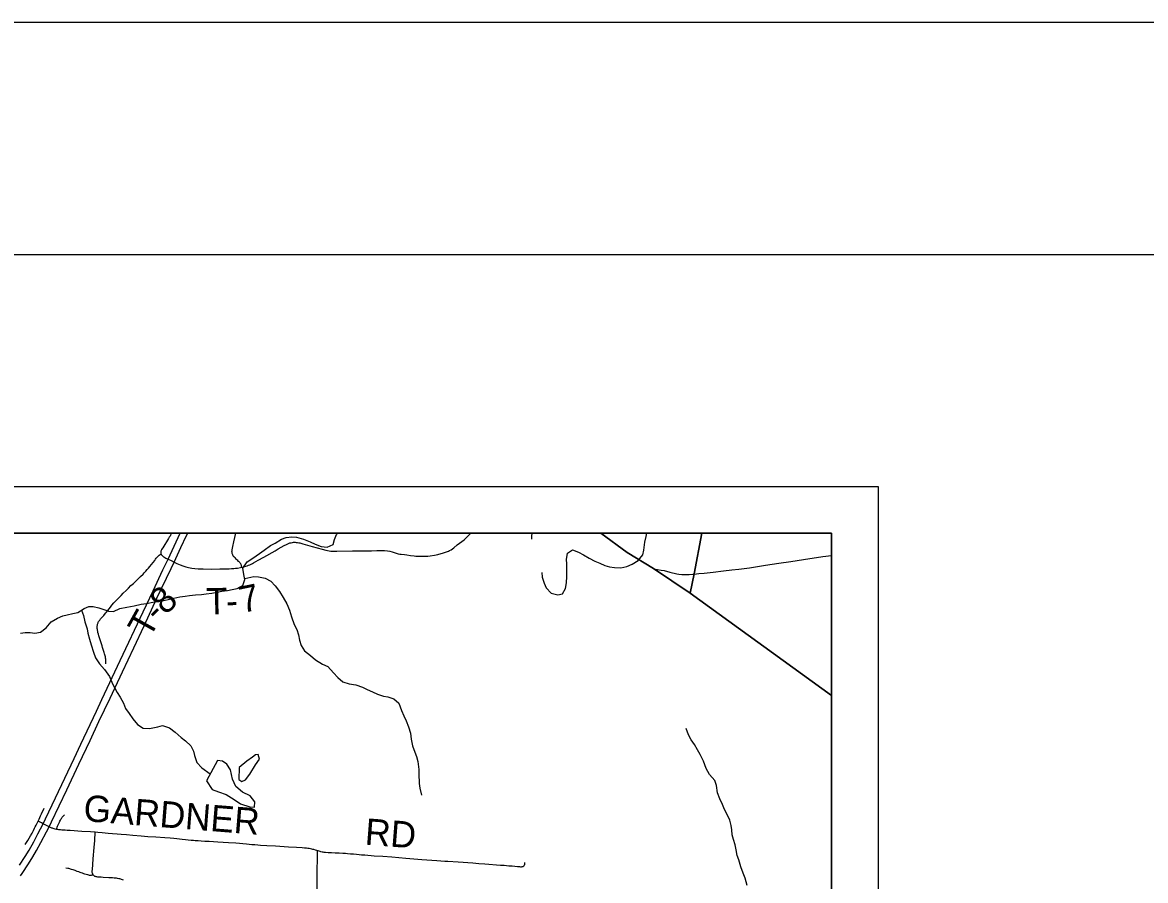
# Model space of a CAD drawing. Extents: x 0 to 34, y 0 to 22.
# Drawn here: x 7.37 to 9.791, y 20.151 to 22 of the extents above; entities that cross this region are included whole.
import ezdxf

# ---------------------------------------------------------------- set-up
doc = ezdxf.new("R2010")
doc.units = 0
for name, color, linetype in [('Default', 7, 'Continuous'), ('GM_X_Minor_Lake', 7, 'Continuous'), ('GM_X_Minor_River', 7, 'Continuous'), ('GM_X_Township_Road', 7, 'Continuous'), ('GM_X_Township_Road_Text', 7, 'Continuous'), ('GM_X_US_Route', 7, 'Continuous'), ('SH_Border', 7, 'Continuous'), ('SH_Cut_Line', 7, 'Continuous'), ('SH_Data', 7, 'Continuous')]:
    doc.layers.add(name, color=color, linetype=linetype)

msp = doc.modelspace()

# ---------------------------------------------------------------- linework, layer by layer
at = {"layer": 'Default'}
msp.add_lwpolyline([(9.1142, 17.7402), (9.1142, 20.5497), (8.8095, 20.7701), (8.7304, 20.823), (8.6734, 20.858), (8.6167, 20.8996), (2.3571, 20.8996)], dxfattribs=at)
for points in [[(8.8345, 20.8996), (8.6167, 20.8996), (8.6734, 20.858), (8.7304, 20.823), (8.8095, 20.7701), (8.8178, 20.8117)], [(9.1142, 20.5497), (9.1142, 20.8996), (8.8345, 20.8996), (8.8178, 20.8117), (8.8095, 20.7701)]]:
    msp.add_lwpolyline(points, close=True, dxfattribs=at)
at = {"layer": 'GM_X_Minor_Lake'}
for points in [[(7.7666, 20.3654), (7.7788, 20.3471), (7.7928, 20.342), (7.8094, 20.3364), (7.8263, 20.3256), (7.8399, 20.3159), (7.8602, 20.3092), (7.8705, 20.3087), (7.8706, 20.3201), (7.8605, 20.3335), (7.8443, 20.3413), (7.8301, 20.3532), (7.8227, 20.3689), (7.8184, 20.389), (7.8106, 20.4016), (7.8012, 20.4078), (7.7906, 20.4095)], [(7.7906, 20.4095), (7.7666, 20.3654)], [(7.8367, 20.3683), (7.8431, 20.3644), (7.8511, 20.3677), (7.8604, 20.3797), (7.872, 20.3997), (7.8809, 20.4121), (7.8784, 20.4223), (7.8727, 20.4217), (7.8661, 20.4164), (7.8535, 20.4079), (7.8371, 20.3945)], [(7.8371, 20.3945), (7.8367, 20.3683)]]:
    msp.add_lwpolyline(points, dxfattribs=at)
at = {"layer": 'GM_X_Minor_River'}
for points in [[(7.3968, 20.684), (7.4093, 20.6861), (7.4212, 20.6954), (7.4316, 20.7085), (7.4453, 20.7163), (7.4572, 20.7211), (7.4667, 20.7236), (7.4788, 20.7265), (7.4891, 20.7282), (7.5029, 20.7372), (7.5128, 20.7412), (7.5226, 20.7414), (7.5347, 20.7386), (7.5453, 20.7351), (7.5555, 20.7311), (7.5665, 20.7306), (7.5798, 20.7369), (7.595, 20.7401), (7.611, 20.7429), (7.6258, 20.7461), (7.6372, 20.7475), (7.6509, 20.7503), (7.6608, 20.7517), (7.671, 20.7535), (7.6843, 20.7567), (7.6961, 20.7592), (7.7094, 20.7621), (7.7204, 20.7634), (7.7303, 20.7648), (7.7428, 20.7662), (7.7561, 20.7675), (7.766, 20.7689), (7.7781, 20.7703), (7.7895, 20.772), (7.7998, 20.7741), (7.8119, 20.7759), (7.8218, 20.7776), (7.8329, 20.7801), (7.8454, 20.7864), (7.8494, 20.7996), (7.8473, 20.8103), (7.8452, 20.8236), (7.8541, 20.8375), (7.8667, 20.8457), (7.8812, 20.8553), (7.8908, 20.8624), (7.9049, 20.8725), (7.9145, 20.878), (7.9282, 20.8862), (7.9385, 20.8902), (7.9507, 20.8912), (7.9605, 20.8907), (7.9756, 20.8863), (7.9899, 20.8804), (8.0009, 20.8754), (8.0137, 20.8706), (8.0266, 20.8689), (8.0395, 20.8748), (8.0423, 20.8858), (8.0466, 20.8967), (8.0496, 20.8996)], [(8.4683, 20.8861), (8.4682, 20.893), (8.4687, 20.8996)], [(8.4895, 20.8146), (8.4902, 20.8048), (8.4942, 20.7915), (8.4986, 20.7815), (8.5098, 20.77), (8.5238, 20.7664), (8.5337, 20.7689), (8.5403, 20.7799), (8.5427, 20.792), (8.5436, 20.8056), (8.5434, 20.82), (8.5436, 20.8329), (8.543, 20.8428), (8.5447, 20.856), (8.5558, 20.8634), (8.5682, 20.8583), (8.5791, 20.8525), (8.5912, 20.8452), (8.6036, 20.8393), (8.6145, 20.8346), (8.6251, 20.8299), (8.6353, 20.8271), (8.6463, 20.8255), (8.6599, 20.8249), (8.6724, 20.8274), (8.6843, 20.8322), (8.6969, 20.8407), (8.7069, 20.8527), (8.7093, 20.8629), (8.7118, 20.8796), (8.7142, 20.8921), (8.7161, 20.8996)], [(7.849, 20.8018), (7.8684, 20.8058), (7.8787, 20.8049), (7.8934, 20.8021), (7.9055, 20.7959), (7.9144, 20.7859), (7.9241, 20.7736), (7.9319, 20.7606), (7.9401, 20.7469), (7.9456, 20.7331), (7.9496, 20.7191), (7.9555, 20.7023), (7.9614, 20.6916), (7.965, 20.6802), (7.9675, 20.6688), (7.9708, 20.6574), (7.9779, 20.6459), (7.9906, 20.6355), (8.0019, 20.6266), (8.0169, 20.6173), (8.0282, 20.6118), (8.0406, 20.5984), (8.0499, 20.5884), (8.0608, 20.5788), (8.0744, 20.5748), (8.0884, 20.5724), (8.1031, 20.5676), (8.1133, 20.5622), (8.1246, 20.5575), (8.1351, 20.5524), (8.148, 20.5481), (8.1578, 20.5464), (8.1703, 20.5421), (8.1815, 20.5328), (8.187, 20.5172), (8.1918, 20.5054), (8.197, 20.4947), (8.2021, 20.4817), (8.2065, 20.468), (8.2078, 20.4551), (8.2111, 20.4407), (8.2158, 20.4273), (8.2195, 20.4178), (8.222, 20.4072), (8.2241, 20.3901), (8.2247, 20.3806), (8.2252, 20.3601), (8.2262, 20.3498), (8.2302, 20.335)], [(7.4971, 20.7334), (7.5015, 20.7216), (7.5048, 20.7083), (7.5095, 20.6935), (7.5113, 20.6836), (7.5149, 20.6706), (7.5182, 20.6585), (7.5233, 20.6429), (7.5277, 20.6303), (7.5358, 20.618), (7.5467, 20.6058), (7.5575, 20.5904), (7.5641, 20.5748), (7.5741, 20.5557), (7.5808, 20.5458), (7.5875, 20.5332), (7.5922, 20.5217), (7.5997, 20.511), (7.6079, 20.4991), (7.618, 20.4869), (7.63, 20.4791), (7.6436, 20.4782), (7.6615, 20.4817), (7.6722, 20.485), (7.6869, 20.4799), (7.6989, 20.4706), (7.712, 20.4591), (7.7218, 20.4521), (7.733, 20.441), (7.7386, 20.4295), (7.7411, 20.42), (7.7462, 20.4051), (7.7567, 20.3933), (7.7748, 20.3806)], [(7.3661, 20.684), (7.3759, 20.685), (7.3866, 20.6849), (7.3968, 20.684)], [(8.9318, 20.1403), (8.9278, 20.1559), (8.9234, 20.1665), (8.9182, 20.1799), (8.9139, 20.1951), (8.9106, 20.2046), (8.9081, 20.2172), (8.9063, 20.2274), (8.9027, 20.2392), (8.8998, 20.2495), (8.8988, 20.2598), (8.8974, 20.2693), (8.8945, 20.2807), (8.8897, 20.2917), (8.883, 20.304), (8.8786, 20.3143), (8.8735, 20.3268), (8.8683, 20.3398), (8.8663, 20.3554), (8.8626, 20.3664), (8.851, 20.3791), (8.844, 20.3921), (8.8381, 20.4077), (8.8307, 20.4226), (8.8248, 20.4325), (8.8188, 20.4436), (8.8114, 20.4539), (8.8055, 20.4646), (8.8007, 20.478)]]:
    msp.add_lwpolyline(points, dxfattribs=at)
at = {"layer": 'GM_X_Township_Road'}
for points in [[(7.6911, 20.8996), (7.691, 20.8993), (7.6905, 20.8979), (7.6899, 20.8965), (7.689, 20.8948), (7.6881, 20.8932), (7.6866, 20.8906), (7.6851, 20.8881), (7.6724, 20.868), (7.67, 20.8643), (7.6694, 20.8632), (7.6689, 20.862), (7.6685, 20.8608), (7.6682, 20.8597), (7.6682, 20.8588), (7.6682, 20.8577), (7.6682, 20.8565), (7.6685, 20.8555), (7.6688, 20.8544)], [(7.8426, 20.826), (7.8424, 20.8272), (7.8421, 20.8293), (7.8418, 20.8308), (7.8413, 20.8321), (7.8407, 20.8332), (7.84, 20.8341), (7.8393, 20.835), (7.8385, 20.8359), (7.8371, 20.8373), (7.8358, 20.8385), (7.8343, 20.8401), (7.8323, 20.8419), (7.8305, 20.8436), (7.8289, 20.8451), (7.8273, 20.8467), (7.8262, 20.848), (7.8252, 20.8494), (7.8243, 20.8508), (7.8234, 20.8526), (7.8226, 20.8541), (7.8221, 20.8558), (7.8218, 20.8575), (7.8216, 20.8596), (7.8218, 20.8614), (7.822, 20.8633), (7.8235, 20.8706), (7.8254, 20.8803), (7.8276, 20.89), (7.8302, 20.8996)], [(7.8426, 20.826), (7.8467, 20.827), (7.8545, 20.8292), (7.8575, 20.8302), (7.8603, 20.8313), (7.8632, 20.8325), (7.8657, 20.8337), (7.8681, 20.8351), (7.8778, 20.8408), (7.8902, 20.8478), (7.9145, 20.8616), (7.9215, 20.8657), (7.9339, 20.8727), (7.9389, 20.8752), (7.942, 20.8766), (7.9447, 20.8776), (7.9467, 20.8782), (7.9489, 20.8788), (7.9519, 20.8794), (7.9544, 20.8796), (7.9575, 20.8797), (7.9601, 20.8795), (7.963, 20.8792), (7.9655, 20.8787), (7.9679, 20.8782), (7.9745, 20.8766), (7.9948, 20.8707), (8.0157, 20.8647), (8.0241, 20.8625), (8.0309, 20.8612), (8.0347, 20.8608), (8.0383, 20.8604), (8.0428, 20.8603), (8.0476, 20.8602), (8.0811, 20.8609), (8.1227, 20.8615), (8.1339, 20.8619), (8.1438, 20.8621), (8.1507, 20.8618), (8.1568, 20.8611), (8.1617, 20.8602), (8.1671, 20.8588), (8.1802, 20.8549), (8.1832, 20.8542), (8.1863, 20.8538), (8.1937, 20.8531), (8.1986, 20.8524), (8.2066, 20.8513), (8.214, 20.8503), (8.2179, 20.85), (8.2218, 20.8498), (8.2266, 20.8496), (8.2322, 20.8495), (8.2386, 20.8497), (8.2435, 20.85), (8.2485, 20.8505), (8.2583, 20.8519), (8.2618, 20.8526), (8.2656, 20.8534), (8.2775, 20.8568), (8.284, 20.8589), (8.2886, 20.8607), (8.2908, 20.8618), (8.294, 20.8636), (8.2972, 20.8658), (8.3001, 20.868), (8.3073, 20.8739), (8.3171, 20.8815), (8.3219, 20.8853), (8.3271, 20.8899), (8.3361, 20.8983), (8.3374, 20.8996)], [(7.55, 20.6175), (7.55, 20.6194), (7.55, 20.6215), (7.5499, 20.6238), (7.5497, 20.6259), (7.5495, 20.628), (7.5492, 20.6302), (7.5488, 20.6326), (7.5483, 20.6351), (7.5478, 20.6371), (7.5472, 20.6392), (7.5464, 20.6418), (7.5456, 20.6444), (7.5441, 20.6488), (7.5428, 20.6529), (7.5416, 20.6567), (7.5403, 20.661), (7.5392, 20.6649), (7.5379, 20.6691), (7.5363, 20.6738), (7.535, 20.6778), (7.5338, 20.6815), (7.5327, 20.6856), (7.5322, 20.6881), (7.5319, 20.6899), (7.5316, 20.6917), (7.5314, 20.694), (7.5313, 20.6959), (7.5312, 20.698), (7.5313, 20.6994), (7.5315, 20.7011), (7.5319, 20.7031), (7.5324, 20.7045), (7.5329, 20.706), (7.5334, 20.7074), (7.5342, 20.7088), (7.5351, 20.7102), (7.5365, 20.712), (7.5385, 20.7146), (7.5417, 20.7184), (7.5451, 20.7221), (7.5492, 20.7267), (7.5508, 20.7287), (7.5539, 20.7325), (7.5568, 20.7364), (7.5596, 20.7401), (7.5629, 20.7441), (7.5673, 20.7491), (7.5729, 20.7552), (7.5826, 20.7652), (7.5874, 20.7699), (7.5934, 20.7758), (7.5987, 20.7811), (7.604, 20.7862), (7.6093, 20.791), (7.6205, 20.8016), (7.6246, 20.8056), (7.6299, 20.8109), (7.6326, 20.8139), (7.6358, 20.8174), (7.6391, 20.821), (7.6415, 20.8238), (7.6447, 20.8275), (7.6482, 20.8317), (7.6516, 20.8358), (7.6552, 20.8406), (7.6568, 20.8431), (7.6585, 20.8452), (7.6599, 20.8471), (7.6611, 20.8485), (7.6622, 20.8495), (7.6632, 20.8505), (7.6649, 20.8518), (7.6668, 20.8531), (7.6688, 20.8544)], [(7.6688, 20.8544), (7.6692, 20.8535), (7.67, 20.8524), (7.671, 20.8513), (7.6719, 20.8504), (7.6732, 20.8494), (7.6745, 20.8485), (7.6791, 20.8458), (7.6838, 20.8434)], [(7.6838, 20.8434), (7.6904, 20.8401), (7.6968, 20.8368)], [(8.818, 20.8112), (8.8277, 20.8121), (8.8395, 20.8134), (8.8586, 20.8155), (8.8814, 20.8182), (8.8993, 20.8204), (8.9141, 20.822), (8.9369, 20.8249), (8.9584, 20.8281), (8.9718, 20.8302), (9.0001, 20.8345), (9.0265, 20.8385), (9.0535, 20.8427), (9.0953, 20.8489), (9.1142, 20.8515)], [(7.6968, 20.8368), (7.7031, 20.8338), (7.7097, 20.8308), (7.7158, 20.8286), (7.7219, 20.8269), (7.7281, 20.8254), (7.7315, 20.8246), (7.7348, 20.824), (7.7418, 20.8231), (7.749, 20.8226), (7.7595, 20.8222), (7.7769, 20.822), (7.7955, 20.8222), (7.8154, 20.8227), (7.8204, 20.823), (7.8253, 20.8233), (7.8293, 20.8237), (7.8333, 20.8242), (7.8401, 20.8254), (7.8426, 20.826)], [(8.7307, 20.8225), (8.7469, 20.8197), (8.753, 20.8186), (8.7657, 20.8156), (8.7808, 20.8119), (8.7851, 20.8111), (8.7912, 20.8102), (8.7948, 20.8099), (8.7986, 20.8099), (8.8073, 20.8102), (8.8148, 20.8109), (8.818, 20.8112)], [(7.4041, 20.2788), (7.406, 20.2829), (7.4076, 20.2867), (7.409, 20.2902), (7.4109, 20.2944), (7.4169, 20.3065)], [(7.4437, 20.261), (7.4443, 20.2629), (7.445, 20.2654), (7.4458, 20.2676), (7.4463, 20.269), (7.4471, 20.2707), (7.4485, 20.2738), (7.4498, 20.2766), (7.4509, 20.2788), (7.4518, 20.2806), (7.4531, 20.2828), (7.4542, 20.2847), (7.4559, 20.2872), (7.4573, 20.2889), (7.4583, 20.2901), (7.4592, 20.2911), (7.4606, 20.2923)], [(7.3762, 20.2284), (7.3815, 20.2369), (7.3846, 20.2422), (7.3874, 20.2471), (7.3907, 20.2531), (7.3935, 20.2587), (7.3958, 20.2633), (7.3976, 20.2667), (7.3995, 20.2702), (7.4041, 20.2788)], [(7.4144, 20.2732), (7.4111, 20.2749), (7.4079, 20.2766), (7.4041, 20.2788)], [(7.4277, 20.2665), (7.4217, 20.2696), (7.4144, 20.2732)], [(8.4524, 20.1899), (8.4523, 20.1879), (8.4522, 20.1865), (8.4521, 20.1855), (8.4518, 20.1845), (8.4515, 20.1835), (8.451, 20.1827), (8.4504, 20.1819), (8.4497, 20.1813), (8.4492, 20.1809), (8.4484, 20.1804), (8.4473, 20.1801), (8.4464, 20.1799), (8.4451, 20.1798), (8.4439, 20.1798), (8.4418, 20.1799), (8.4368, 20.1803), (8.4253, 20.1813), (8.4187, 20.182), (8.4082, 20.1829), (8.4006, 20.1834), (8.3665, 20.186), (8.3535, 20.187), (8.3411, 20.1879), (8.3089, 20.1902), (8.2872, 20.1916), (8.2802, 20.192), (8.2719, 20.1926), (8.2631, 20.1932), (8.2526, 20.1939), (8.2308, 20.1956), (8.1967, 20.1982), (8.1664, 20.2007), (8.1466, 20.2022), (8.128, 20.2035), (8.1213, 20.204), (8.1144, 20.2045), (8.1078, 20.205), (8.1011, 20.2055), (8.0958, 20.206), (8.0902, 20.2065), (8.0834, 20.2072), (8.077, 20.2078), (8.0709, 20.2083), (8.0663, 20.2087), (8.0609, 20.209), (8.0525, 20.2094), (8.0444, 20.2097), (8.0362, 20.2101), (8.0289, 20.2106), (8.0232, 20.211), (8.0207, 20.2113), (8.0184, 20.2116), (8.0162, 20.212), (8.0135, 20.2126), (8.0115, 20.2131), (8.0095, 20.2137), (8.0071, 20.2144), (8.0062, 20.2147), (8.0046, 20.2153), (8.0015, 20.2163), (7.9984, 20.2173), (7.9961, 20.2179), (7.9938, 20.2185), (7.9909, 20.2191), (7.988, 20.2196), (7.9851, 20.22), (7.9823, 20.2203), (7.9782, 20.2207), (7.9732, 20.221), (7.9609, 20.2218), (7.9433, 20.2227), (7.9151, 20.2244), (7.8969, 20.2254), (7.8829, 20.2263), (7.8776, 20.2267), (7.8709, 20.2273), (7.8642, 20.2279), (7.8527, 20.229), (7.8303, 20.2309), (7.8142, 20.232), (7.8024, 20.2328), (7.7914, 20.2335), (7.7819, 20.234), (7.7722, 20.2345), (7.7634, 20.235), (7.7555, 20.2355), (7.7485, 20.236), (7.7426, 20.2364), (7.7386, 20.2368), (7.7334, 20.2373), (7.7274, 20.238), (7.7214, 20.2387), (7.7146, 20.2394), (7.7087, 20.24), (7.7031, 20.2406), (7.696, 20.2412), (7.6881, 20.2418), (7.677, 20.2425), (7.6572, 20.2438), (7.6403, 20.2452), (7.6257, 20.2462), (7.6082, 20.2477), (7.5942, 20.2489), (7.5828, 20.2498), (7.5744, 20.2506), (7.5644, 20.2514), (7.5548, 20.2522), (7.5417, 20.2534), (7.5326, 20.2541), (7.5266, 20.2546), (7.5165, 20.2553), (7.4983, 20.2566), (7.4729, 20.2582), (7.4663, 20.2586), (7.4618, 20.259), (7.4549, 20.2595), (7.4522, 20.2597), (7.4498, 20.26), (7.4482, 20.2602), (7.4461, 20.2605), (7.4437, 20.261), (7.4405, 20.2616), (7.4382, 20.2622), (7.4364, 20.2627), (7.4349, 20.2633), (7.4334, 20.2639), (7.4277, 20.2665)], [(7.5876, 20.1513), (7.5854, 20.1523), (7.5836, 20.1531), (7.5818, 20.1537), (7.5798, 20.1542), (7.5776, 20.1547), (7.5752, 20.1552), (7.5725, 20.1556), (7.568, 20.156), (7.5643, 20.1563), (7.556, 20.1568), (7.5443, 20.1574), (7.5398, 20.1577), (7.5355, 20.1579), (7.5327, 20.1582), (7.5305, 20.1584), (7.529, 20.1587), (7.5277, 20.1592), (7.5263, 20.1597), (7.5254, 20.1603), (7.5245, 20.161), (7.524, 20.1615), (7.5231, 20.1624), (7.5225, 20.1632), (7.5218, 20.1642), (7.5214, 20.1649), (7.521, 20.1657), (7.5208, 20.1667), (7.5206, 20.1682), (7.5206, 20.1707), (7.5208, 20.1745), (7.5216, 20.1852), (7.5227, 20.1975), (7.5248, 20.222), (7.5257, 20.2368), (7.5266, 20.2546)], [(8.0033, 20.009), (8.0034, 20.0252), (8.0035, 20.0518), (8.0042, 20.0792), (8.0047, 20.1084), (8.0052, 20.1345), (8.0056, 20.1693), (8.0061, 20.2014), (8.0062, 20.2147)], [(7.4636, 20.1784), (7.4678, 20.1775), (7.4696, 20.177), (7.4711, 20.1766), (7.4729, 20.176), (7.475, 20.1754), (7.4785, 20.1742), (7.4827, 20.1728), (7.4874, 20.1711), (7.4909, 20.1699), (7.4938, 20.1689), (7.4962, 20.168), (7.4989, 20.1671), (7.5014, 20.1662), (7.5038, 20.1654), (7.5075, 20.1642), (7.5099, 20.1634), (7.5121, 20.1628), (7.5136, 20.1625), (7.5149, 20.1623), (7.5169, 20.1622), (7.5189, 20.1624), (7.5205, 20.1627), (7.5225, 20.1632)]]:
    msp.add_lwpolyline(points, dxfattribs=at)
at = {"layer": 'GM_X_US_Route'}
for points in [[(7.3638, 20.1836), (7.3759, 20.2024), (7.3842, 20.2163), (7.3943, 20.2342), (7.4034, 20.2512), (7.4144, 20.2732), (7.4199, 20.284), (7.4413, 20.3288), (7.4611, 20.371), (7.4815, 20.4136), (7.496, 20.4445), (7.5294, 20.516), (7.541, 20.5407), (7.581, 20.6249), (7.6301, 20.7295), (7.6517, 20.7749), (7.6727, 20.82), (7.6838, 20.8434), (7.697, 20.871), (7.7103, 20.8996)], [(7.6968, 20.8368), (7.7115, 20.8682), (7.7239, 20.8946), (7.7262, 20.8996)], [(7.4277, 20.2665), (7.4328, 20.2771), (7.4656, 20.3461), (7.4914, 20.4013), (7.5157, 20.4523), (7.5349, 20.4934), (7.559, 20.5438), (7.5854, 20.6007), (7.61, 20.6523), (7.6321, 20.6996), (7.66, 20.7592), (7.6903, 20.8232), (7.6968, 20.8368)], [(7.3657, 20.1608), (7.3691, 20.1657), (7.3831, 20.187), (7.3923, 20.2017), (7.4005, 20.2156), (7.4099, 20.2324), (7.422, 20.2555), (7.4277, 20.2665)]]:
    msp.add_lwpolyline(points, dxfattribs=at)
at = {"layer": 'SH_Border'}
msp.add_lwpolyline([(1.5, 21.5), (33.5, 21.5), (33.5, 0.5), (1.5, 0.5)], close=True, dxfattribs=at)
at = {"layer": 'SH_Cut_Line'}
msp.add_lwpolyline([(0, 0), (34, 0), (34, 22), (0, 22)], close=True, dxfattribs=at)
msp.add_lwpolyline([(9.1142, 14.0996), (9.1142, 20.8996), (2.3142, 20.8996)], dxfattribs=at)
at = {"layer": 'SH_Data'}
for p, q in [((2.2142, 20.9996), (9.2142, 20.9996)), ((9.2142, 20.9996), (9.2142, 13.9996)), ((2.3142, 20.8996), (9.1142, 20.8996)), ((9.1142, 20.8996), (9.1142, 14.0996))]:
    msp.add_line(p, q, dxfattribs=at)

# ---------------------------------------------------------------- texts
at = {"layer": 'GM_X_Township_Road_Text'}
for s, height, rotation, p in [('8', 0.0568, 45.0863, (7.6788, 20.7211)), ('T', 0.0568, 0.9772, (7.7661, 20.7241)), ('7', 0.0568, 11.8225, (7.8434, 20.727)), ('-', 0.0568, 2.1926, (7.8099, 20.7249)), ('T', 0.0568, 60.8659, (7.644, 20.6707)), ('-', 0.0568, 45, (7.6622, 20.7045)), ('GARDNER', 0.05682, 355.4821, (7.5001, 20.2791)), ('RD', 0.05682, 355.6076, (8.1068, 20.2282))]:
    msp.add_text(s, height=height, rotation=rotation, dxfattribs=at).set_placement(p)

doc.saveas('drawing.dxf')
